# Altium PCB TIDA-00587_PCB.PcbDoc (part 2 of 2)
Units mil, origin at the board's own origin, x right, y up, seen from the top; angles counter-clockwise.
Board outline 4500 x 1700 mil, 4 copper layers (Top Layer, MidLayer1, MidLayer2, Bottom Layer), stack 61.6 mil thick; 120 components, 70 nets, 360 pads, 146 vias.
Unrouted connection lines stored in the file: 1.
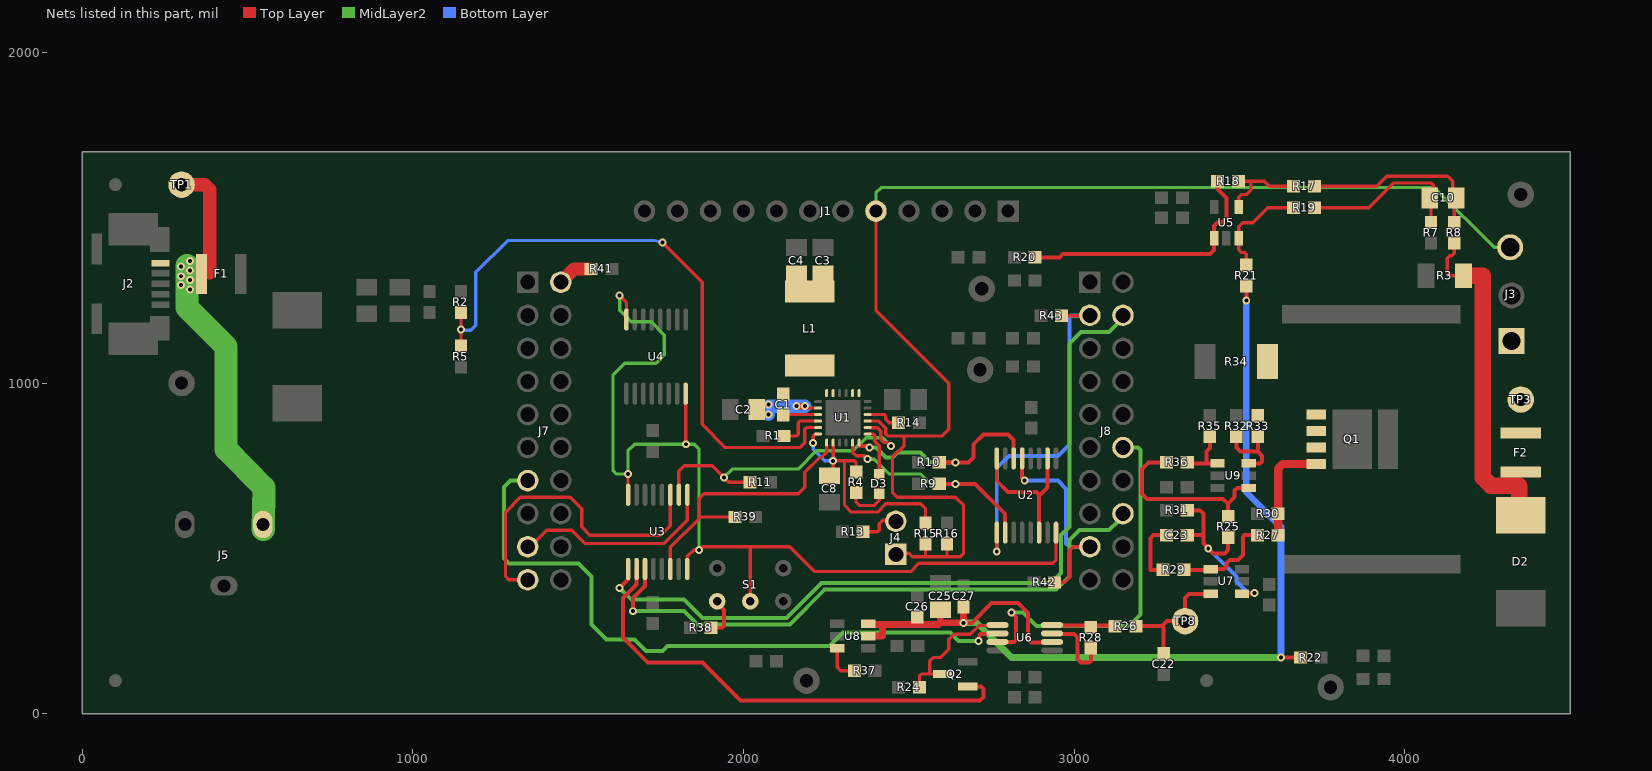
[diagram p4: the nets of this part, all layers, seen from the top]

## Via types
v1: diameter 24, hole 12, Top Layer to Bottom Layer, 141 vias
v2: diameter 50, hole 28, Top Layer to Bottom Layer, 4 vias
v3: diameter 50, hole 28, Top Layer to Bottom Layer, tented bottom, 1 vias

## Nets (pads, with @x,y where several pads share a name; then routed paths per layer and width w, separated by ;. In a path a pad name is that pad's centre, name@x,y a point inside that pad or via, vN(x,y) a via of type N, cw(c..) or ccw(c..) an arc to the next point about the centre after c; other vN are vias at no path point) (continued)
I2C_SCL_A: J8.17 R42.2 U2.13 | length 662.5
  Top Layer w10: R42.2@2940.5,397 2971,397 2985,411 2985,492.93 2997.07,505 J8.17@3050,505
  Top Layer w12: U2.13@2842.2,772.2 2842.2,712.8 v1(2850,705)
  Bottom Layer w12: v1(2850,705) 2950,705 2975,680 2975,515 2985,505 3025,505 J8.17@3050,480
I2C_SDA_A: J8.3 R43.2 U2.1 | length 1111.3
  Top Layer w10: R43.2@2961.5,1204 3049,1204 J8.3@3050,1205
  Top Layer w12: v1(2765.43,490.43) U2.1@2765.43,547.8
  Bottom Layer w12: v1(2765.43,490.43) 2765.43,743.24 2802.2,780 2950.82,780 2985,814.18 2985,1200 2990,1205 3025,1205 J8.3@3050,1180
INT_1: J7.19 U3.3 | length 982
  Top Layer w10: J7.19@1350,380 1325,405 1290,405 1280,415 1280,610 1325,655 1475,655 1510,620 1510,565 1535,540 1750,540 1778.39,568.39 U3.3@1778.39,662.2
INT_2: J7.17 U3.1 | length 644.9
  Top Layer w10: J7.17@1350,480 1350,500 1405,555 1480,555 1520,515 1759.13,515 1829.57,585.43 U3.1@1829.57,662.2
LDO: C8.2 R4.1 R15.2 U1.2 U1.24 | length 759.2
  Top Layer w10: v1@2210.49,820 2210,820.49 2210,840 2215.79,845.79 U1.24@2225.2,845.79 ; C8.2@2270.47,720.47 v1(2270.47,765) ; U1.2@2270.47,810 v1(2270.47,765) ; 2340,751.5 2340,759.98 2334.98,765 2305,765 ; R15.2@2550,566.5 R15.2@2550,576.5 2550,620 2535,635 2430,635 2405,610 2325,610 2305,630 2305,765 ; v1(2270.47,765) 2305,765
  Bottom Layer w10: v1(2210.25,818.55) 2210.25,799.75 2245,765 v1(2270.47,765)
NetC1_1: C1.1 L1.1 U1.17 U1.18
NetC1_2: C1.2 U1.21 | length 95
  Top Layer w10: C1.2@2120,905 U1.21@2215,905
NetC2_2: C2.2 U1.20 | length 202.3
  Top Layer w10: v1@2180,930 2185.47,924.53 U1.20@2215,924.53
  Top Layer w20: v1(2160,930) v1(2185,930)
  Bottom Layer w25: v1@2075,930 v1(2075,935)
  Bottom Layer w40: v1(2075,905) 2075,930 v1(2185,930)
NetC3_1: C3.1 C4.1 L1.2 U1.13 U1.14
NetC10_1: C10.1 R8.1 R17.2 | length 565.6
  Top Layer w10: R17.2@3726.5,1595 3915,1595 3945,1625 4130,1625 4144.53,1610.47 C10.1@4144.53,1560 ; C10.1@4148.23,1564.45 4148.7,1563.98 R8.1@4148.7,1485.94
NetC10_2: C10.2 R7.1 R19.2 | length 509.4
  Top Layer w10: R19.2@3726.5,1530 3890,1530 3965,1605 4080,1605 4085.47,1599.53 C10.2@4085.47,1560.75 ; R7.1@4078.7,1485.94 4078.7,1553.98 C10.2@4085.47,1560.75 ; C10.2@4085.47,1560 C10.2@4085.47,1560.75
NetC22_1: C22.1 R26.2 TP8.1 U7.3 | length 395.7
  Top Layer w12: R26.2@3186.5,265 3265,265 ; C22.1@3270,181.5 3270,260 3265,265 ; U7.3@3415,363 3414,362 3347,362 3335,350 TP8.1@3335,280 3280,280 3265,265
NetC23_1: C23.1 R29.1 | length 186.1
  Top Layer w12: R29.1@3268.5,435 3230,435 3230,530 3240,540 C23.1@3278.5,540
NetC23_2: C23.2 R25.2 R31.1 U7.4 | length 569.8
  Top Layer w12: C23.2@3341.5,540 3390,540 ; R31.1@3341.5,615 3380,615 3390,605 3390,540 ; R25.2@3465,533.5 3465,495 3455,485 3420,485 v1(3405,500) 3390,515 3390,540 ; U7.4@3502,363 3538,363 3540,365 v1(3545,365)
  Bottom Layer w12: v1(3405,500) 3490,415 3490,400 3525,365 v1(3545,365)
NetD2_1: D2.1 F2.1 R3.2 R8.2 | length 1023.6
  Top Layer w10: R8.2@4148.7,1422.95 4148.7,1392.13 4141.57,1385 4135,1385 4128,1378 4128,1336.13 4139.69,1324.45 R3.2@4177.09,1324.45
  Top Layer w50: R3.2@4177.09,1324.45 4235.55,1324.45 4235.55,714.07 4259.62,690 4346,690 4346,614.49 D2.1@4350,610.49
NetD3_1: D3.1 R4.2 | length 149.3
  Top Layer w10: R4.2@2340,673.5 R4.2@2340,668.5 2340,640 2350,630 2395,630 2410,645 D3.1@2410,665.47 D3.1@2410,680.47
NetD3_2: D3.2 U1.7 | length 131
  Top Layer w10: U1.7@2374.8,845.79 2392.21,845.79 2396,842 2396,824 2410,810 D3.2@2410,739.53
NetF1_1: F1.1 J2.1 J5.1 TP1.1 | length 1279.8
  Top Layer w12: F1.1@360.94,1330 F1.1@360.94,1374.06
  Top Layer w40: TP1.1@300,1600 370,1600 385,1585 385,1333
  MidLayer2 w70: 317,1355 317,1312 317,1228 435,1110 435,800 549,684 J5.1@547,558
  other v1: 325,1283 299,1297 325,1312 299,1323 325,1340 299,1352 325,1369
NetF2_2: F2.2 J3.1 TP3.1
NetJ1_5: J1.5 J3.3 J4.1 R15.1 R16.2 U1.9 | length 3947.3
  Top Layer w10: U1.9@2379.76,885.2 2385,885.2 2408.59,885.2 2430,863.79 2430,845 2435,840 2485,840 ; J1.5@2400,1520 2400,1220 2620,1000 2620,860 2600,840 2485,840 ; J4.1@2460,485 2500,485 2510,475 2550,475 ; R15.1@2550,503.5 2550,475 ; R16.2@2615,503.5 2615,475 ; 2485,840 2485,810 2450,775 2450,670 2465,655 2640,655 2665,630 2665,485 2655,475 2615,475 ; 2550,475 2615,475
  MidLayer2 w10: J1.5@2400,1520 2400,1575 2416.3,1591.3 4088.7,1591.3 4269.41,1410.59 J3.3@4350,1410.59
NetJ4_2: J4.2 R13.2 | length 124.7
  Top Layer w10: R13.2@2361.5,550 2405,550 2410,555 2410,575 2420,585 J4.2@2460,585
NetJ7_2: J7.2 R41.2 | length 108.1
  Top Layer w40: J7.2@1447,1305 1487,1345 R41.2@1538.5,1345
NetQ1_1: Q1.1 Q1.2 Q1.3 R33.2 R34.2
NetQ1_4: Q1.4 R27.2 R30.2 | length 321.9
  Top Layer w25: R27.2@3616.5,540 R30.2@3616.5,605 3616.5,741.5 3630,755 Q1.4@3731.34,755
NetQ2_3: Q2.3 R24.2 U6.5 | length 420.4
  Top Layer w10: R24.2@2531.5,80 2531.5,113.76 2537.74,120 2563.23,120 ; Q2.3@2602.6,120 2563.23,120 ; U6.5@2774.4,266.8 2711.8,266.8 2685,240 2635,240 2620,225 2620,195 2595,170 2573.23,170 2563.23,160 2563.23,120
NetR1_2: R1.2 U1.22 | length 137.7
  Top Layer w10: R1.2@2121.5,840 2160,840 2165,845 2165,880 2170,885 U1.22@2220.04,885
NetR2_1: R2.1 R5.2 U1.23 | length 1937.8
  Top Layer w10: R5.2@1145,1110 R5.2@1145,1111.5 v1(1145,1162.5) R2.1@1145,1213.5 ; v1(1755,1425) 1875,1305 1875,875 1945,805 2170,805 2185,820 2185,860 2190.5,865.5 U1.23@2215,865.5
  Bottom Layer w10: v1(1145,1162.5) 1147.5,1160 1175,1160 1190,1175 1190,1335 1286,1431 1662.61,1431 1670.43,1431 ; 1671.04,1431 1731,1431 v1(1755,1425)
NetR14_2: R14.2 U1.10 | length 105.1
  Top Layer w10: U1.10@2379.65,905 2425,905 2430,900 2430,890.02 2440.02,880 R14.2@2468.5,880
NetR17_1: R17.1 R18.1 U5.4 | length 279.6
  Top Layer w10: R18.1@3491.5,1610 R18.1@3496.5,1610 3533.25,1610 ; U5.4@3497.4,1532.24 3497.4,1562.4 3505,1570 3520,1570 3533.25,1583.25 3533.25,1610 ; R17.1@3663.5,1595 3590,1595 3575,1610 3533.25,1610
NetR18_2: R18.2 R20.2 U5.1 | length 791.7
  Top Layer w12: R20.2@2881.5,1380 2955,1380 2965,1390 3410,1390 3422.6,1402.6 U5.1@3422.6,1437.76 3422.6,1475.16 3432.44,1485 3445,1485 3460,1500 3460,1560 3433.5,1586.5 R18.2@3433.5,1610
NetR19_1: R19.1 R21.1 U5.3 | length 321.2
  Top Layer w10: R21.1@3520,1356.5 3520,1390 3515,1395 3505,1395 3497.4,1402.6 U5.3@3497.4,1437.76 3497.4,1472.56 3509.84,1485 3540,1485 3585,1530 R19.1@3663.5,1530
NetR25_1: R25.1 R36.1 U9.1 | length 559.3
  Top Layer w12: R36.1@3278.5,760 3225,760 3205,740 3205,665 3220,650 3450,650 3465,635 ; R25.1@3465,596.5 3465,635 ; U9.1@3525,683 3493,683 3485,675 3485,655 3465,635
NetR26_1: R26.1 R28.2 U6.4 | length 181.5
  Top Layer w12: U6.4@2940.2,266.8 R26.1@3121.7,266.8
NetR27_1: R27.1 R29.2 U7.1 | length 303.6
  Top Layer w12: R29.2@3331.5,435 3413,435 3415,437 3452,437 3460,445 3460,455 3470,465 3495,465 3510,480 3510,535 3515,540 R27.1@3553.5,540
NetR28_1: R28.1 U6.3 | length 224.2
  Top Layer w12: U6.3@2940.2,241.2 2998.8,241.2 3010,230 3010,165 3020,155 3045,155 3050,160 R28.1@3050,198.5
NetR32_1: R32.1 R33.1 U9.3 | length 229.8
  Top Layer w12: R32.1@3490,838.5 3490,805 3502,793 3555,793 ; U9.3@3525,757 3562,757 3568,763 3568,780 3555,793 ; R33.1@3555,838.5 3555,793
NetR35_1: R35.1 R36.2 U9.4 | length 183.4
  Top Layer w12: R36.2@3341.5,760 3344.5,757 3400,757 ; R35.1@3410,838.5 3410,803 3400,793 3400,757 ; U9.4@3438,757 3400,757
NetR37_1: R37.1 U8.3 | length 90.7
  Top Layer w10: U8.3@2282.76,197.6 2282.76,140.24 2293,130 2311.82,130
NetR38_1: R38.1 S1.4 | length 123.9
  Top Layer w12: R38.1@1901.5,260 1935,260 1940,265 1940,313.41 1920,333.41 S1.4@1920,340
NetR39_2: R39.2 U1.1 U3.14 | length 836.5
  Top Layer w10: U3.14@1778.39,437.8 1778.39,503.39 1865,590 ; 1865,595 1865,650 1880,665 2165,665 2185,685 2185,730 2229.9,774.9 2234.9,774.9 2251.3,791.3 U1.1@2251.3,810 ; 1870,595 R39.2@1973.5,595
NetS1_5: S1.5 U2.8 U3.8 U3.16 U4.8 U4.16 | length 3150.1
  Top Layer w10: v1(1625,1265) 1645.43,1244.57 U4.8@1645.43,1192.2 ; U3.8@1650.43,662.2 v1@1650.43,724.57 ; U4.16@1824.57,967.8 1824.57,815.43 v1(1825,815) ; U3.16@1829.57,437.8 1829.57,476.14 1848.43,495 v1(1865,495) 1875,505 2020,505 ; S1.5@2020,340 2020,505 ; U2.8@2944.57,547.8 2944.57,464.57 2935,455 2530,455 2505,430 2215,430 2140,505 2020,505
  MidLayer2 w10: v1(1625,1265) 1625,1220 1660,1185 1720,1185 1760,1145 1760,1085 1735,1060 1640,1060 1605,1025 1605,735 1615,725 v1(1650,725) 1650,795 1670,815 v1(1825,815) 1850,815 1865,800 v1(1865,495)
NetU2_6: U2.6 U2.10 U2.16 | length 450.3
  Top Layer w12: U2.16@2765.43,772.2 2765.43,704.57 2800,670 2885,670 2893.39,661.61 ; U2.6@2893.39,547.8 2893.39,661.61 ; U2.10@2918.98,772.2 2918.98,683.98 2896.61,661.61 2893.39,661.61
SCL: R10.1 R11.1 U1.6 U1.8 U2.14 U3.2 | length 1651
  Top Layer w10: U3.2@1803.98,662.2 1803.98,733.98 1820,750 1905,750 v1(1940,715) 1955,700 R11.1@2018.5,700 ; U1.8@2380.28,865 2405,865 2415,855 2415,830 2425,820 2435,820 v1(2445,810)
  Top Layer w12: U1.6@2349.8,810 2375,810 v1(2380,805) ; R10.1@2591.5,760 v1(2640,760) 2680,760 2695,775 2695,815 2725,845 2800,845 2816.61,828.39 U2.14@2816.61,772.2
  MidLayer2 w10: v1(1940,715) 1965,740 2165,740 2220,795 2330.1,795 2370.1,835 2420,835 v1(2445,810)
  MidLayer2 w12: v1(2380,805) 2400,805 2430,775 2450,775 2465,790 2535,790 2565,760 v1(2640,760)
SCLK: J7.13 U6.6 | length 2058.3
  Top Layer w12: v1@2713,220 2713,237.8 2716.4,241.2 U6.6@2774.4,241.2
  MidLayer2 w12: J7.13@1350,680 1325,705 1295,705 1275,685 1275,470 1290,455 1500,455 1540,415 1540,270 1585,225 1670,225 1705,190 1755,190 1770,205 2260,205 2300,245 2625,245 2650,220 v1(2710,220)
SDA: R9.1 U1.5 U2.2 | length 662.7
  Top Layer w10: U1.5@2330.1,810 2330.1,789.9 2340,780 2365,780 v1(2375,770)
  Top Layer w12: R9.1@2591.5,695 v1(2640,695) 2700,695 2791.02,603.98 U2.2@2791.02,547.8
  MidLayer2 w10: v1(2375,770) 2395,770 2440,725 2535,725 2565,695 v1(2640,695)
SIMO: J8.12 U6.7 | length 1141
  Top Layer w12: U6.7@2756.6,216.6 2817.6,216.6 2824,223 2824,292 v1(2810,306)
  MidLayer2 w12: v1(2810,306) 2844,306 2885,265 3165,265 3200,300 3200,797 3192,805 3175,805 J8.12@3150,780
SYNC: Q2.1 U3.10 | length 1473.4
  Top Layer w12: U3.10@1676.02,437.8 1676.02,391.02 1635,350 1635,230 1710,155 1875,155 1990,40 2715,40 2725,50 2725,75 2717.4,82.6 Q2.1@2677.4,82.6
SYNC_1: J8.16 U3.11 | length 1837.4
  Top Layer w12: v1(1665,310) 1665,350 1701.61,386.61 U3.11@1701.61,437.8
  MidLayer2 w12: v1(1665,310) 1820,310 1860,270 2140,270 2245,375 2945,375 2985,415 2985,525 3015,555 3105,555 3130,580 J8.16@3150,580
SYNC_2: J8.4 U3.9 | length 2391.7
  Top Layer w12: v1(1625,380) 1650.43,405.43 U3.9@1650.43,437.8
  MidLayer2 w12: v1(1625,380) 1660,345 1820,345 1875,290 2130,290 2235,395 2930,395 2960,425 2960,540 2985,565 2985,1120 3020,1155 3105,1155 3130,1180 J8.4@3150,1180
VREF: C25.2 C26.1 C27.1 R21.2 R22.2 U6.2 U8.5 U8.6 | length 3086.5
  Top Layer w12: v1(2665,275) 2690,275 2750,335 2830,335 2860,305 2860,225 2869.4,215.6 U6.2@2940.2,215.6 ; v1(3520,1250) R21.2@3520,1293.5 ; v1(3625,170) R22.2@3683.5,170
  Top Layer w20: U8.6@2382,270 2420,270 ; U8.5@2387,235 2420,235 2420,270 ; C26.1@2525,275 C26.1@2525,289.08 ; C25.2@2595,325.47 C25.2@2595,315 2595,275 ; v1@2660,275 2595,275 ; v1(2665,275) C27.1@2665,323.5 ; 2420,270 2590,270 2595,275
  MidLayer2 w20: v1(2665,275) 2705,275 2810,170 v1(3625,170)
  Bottom Layer w20: v1(3520,1250) 3520,670 3625,565 v1(3625,170)
pads on no net: FID1.1 FID2.1 FID3.1 J1.6 J1.7 J1.8 J2.2 J2.3 J2.4 J7.3 J7.5 J7.7 J7.11 J8.1 J8.5 J8.6 J8.7 J8.8 J8.9 J8.10 J8.11 J8.13 J8.14 J8.15 J8.19 LBL1.0 S1.1 S1.3 U2.3 U2.7 U2.9 U2.15 U4.9 U4.10 U4.11

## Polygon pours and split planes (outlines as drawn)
GND on Top Layer "Top Layer-No Net" (solid, pour order 8): 1078.54,1230 828.5,1230 828.5,1048.5 800,1020 410,1020 300,1130 290,1140 290,1240 190,1240 190,1190 110,1190 110,910 150,870 170,850 480,850 530,800 540,810 890,810 1080,1000 1080,1230
GND on Top Layer "Top Layer-No Net 1" (solid, remove dead copper, pour order 7): 21.18,1689 4466.18,1689 4466.18,20 21.18,20
GND on MidLayer1 "MidLayer1-No Net" (solid, pour order 6): 25,1683 4470,1683 4470,30 25,30
GND on MidLayer2 "MidLayer2-No Net" (solid, remove dead copper, pour order 9): 25,1672 4470,1672 4470,25 25,25
GND on Bottom Layer "Bottom Layer-No Net" (solid, remove dead copper, pour order 10): 25,1680 4470,1680 4470,25 25,25

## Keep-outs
Keep-Out Layer:
  lines w10: -20,1715 -15,-15 4515,-15 4515,1715 -20,1715
  text ".Layer_Name" at 577,-858.49 h60

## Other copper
Top Layer:
  rectangle net GND: 2285,935 2315,982
  rectangle net GND: 2285,808 2315,850
  rectangle net GND: 1905,890 1985,950
  rectangle net NetC1_1: 2100,950 2165,1085
  rectangle net NetC2_2: 2010,890 2090,950
  rectangle net NetC1_1: 2245,965 2277,1040
  rectangle net NetC3_1: 2120,1230 2360,1360
  rectangle net 5VDC: 455,1165 779.92,1405
  rectangle net 5VDC: 645,1260 1165,1405
  rectangle net 5VDC: 2175,949.21 2230,1010
  rectangle net NetC3_1: 2324,965 2360,1355
  rectangle net CHG/LOAD: 2370,918 2470,950
  rectangle net NetQ1_1: 3539.21,880 3765,1135.87
  rectangle net NetQ1_1: 3645,785 3765,915
  rectangle net CHG/LOAD: 3780,210 4040,1447.52
  rectangle net CHG/LOAD: 4027.48,1185 4090,1370.71
  rectangle net CHG/LOAD: 4020,210 4170,1260
  rectangle net CHG/LOAD: 3625,1155 3805,1450
  rectangle net CHG/LOAD: 3665,440 3820,723.7
  rectangle net CHG/LOAD: 3630,211.89 3800,475
  rectangle net NetF2_2: 4280.98,834 4415,1185
  rectangle net NetD2_1: 4285,620 4415,750
  rectangle net CHG/LOAD: 2400,918 2482,1105
  rectangle net ADC_CH_VDC: 2690,1030 2835,1153.7
  rectangle net ADC_CH_IDC: 2695,1281.46 2840,1400
  rectangle net GND: 2125,1380 2280,1465
  rectangle net 5VDC: 460,1375 1686.11,1442
  rectangle net GND: 4275,215 4425,385
  rectangle net GND: 3270,975 3465,1220
  rectangle net NetQ1_1: 3510,994.13 3610,1220
  rectangle net GND: 2465,1485 2835,1555
  rectangle net GND: 78.98,1416.14 350,1530
  rectangle net NetF1_1: 284.02,1264.07 405,1391.02
  rectangle net NetF1_1: 209,1352 299,1383
  text ".CopyrightYear" at 1268,1560 h60
  text "TI" at 1544,1560 h60
  text "©" at 1175,1557 h105
  text ".Layer_Name" at 577,-858.49 h60
Bottom Layer:
  text "UL94V-0" at 1575,1545 h60
  text "MADE IN U.S." at 1585,1450 h60
  text ".Layer_Name" at 577,-858.49 h60

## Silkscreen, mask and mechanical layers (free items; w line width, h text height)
Top Overlay:
  text "+" at 194,1575 h40
  text "-" at 4425,1570 h40
  text "-" at 4198,1229 h40
  text "+" at 4199,1108 h40
  text "-" at 194,976 h40
  text "+" at 4375,860 h40
  text "4.5Vdc-6Vdc" at 39,812 h40
  text "Load/Batt" at 4485,690 h40 r90
  text "UNIT 1" at 1880,490 h40
  text "-TS" at 2315,405 h40
  text "UNIT 2" at 1985,250 h40
  text "bq24250RGE" at 668,173 h90
  text "Booster Pack Charger" at 168,56 h90
  text ".Layer_Name" at 577,-858.49 h60
Bottom Overlay:
  rectangle: 219,50 519,150
  text ".PCB_Rev" at 195,70 h60
  text ".PRJ_Number" at 1185,60 h60
  text "-" at 584,49.5 h60
  text ".Layer_Name" at 577,-858.49 h60
Top Paste:
  text ".Layer_Name" at 577,-858.49 h60
Bottom Paste:
  text ".Layer_Name" at 577,-858.49 h60
Top Solder:
  rectangle: 3840,210 3970,255
  text ".Layer_Name" at 577,-858.49 h60
  text ".Layer_Name" at 577,-858.49 h60
Bottom Solder:
  text ".Layer_Name" at 577,-858.49 h60
Drill Guide:
  text ".Layer_Name" at 577,-858.49 h60
M1 Board Outline:
  the board outline again, w10
  text ".Layer_Name" at 577,-858.49 h60
M2 Board Dimensions:
  rectangle: -0.5,-285.5 124.5,-160.5
  rectangle: 124.5,-410.5 499.5,-285.5
  lines w7: -0.5,-285.5 999.5,-285.5 ; 124.5,-410.5 124.5,-160.5 ; 249.5,-410.5 249.5,-160.5 ; 499.5,-410.5 499.5,-160.5 ; 749.5,-410.5 749.5,-160.5 ; -0.5,-410.5 999.5,-410.5 999.5,-160.5 -0.5,-160.5 -0.5,-410.5
  lines w10: -0.5,-475.5 -0.5,-455.5 ; 59.5,-485.5 -0.5,-465.5 ; 59.5,-445.5 -0.5,-465.5 ; 223.58,-465.5 -0.5,-465.5 ; 775.42,-465.5 999.5,-465.5 ; 939.5,-485.5 999.5,-465.5 ; 939.5,-445.5 999.5,-465.5 ; 999.5,-475.5 999.5,-455.5
  text "1000 (mil)" at 233.58,-501.49 h60
  text ".Layer_Name" at 577,-858.49 h60
M3 3D STEP Top:
  text ".Layer_Name" at 577,-858.49 h60
M4 3D STEP Bottom:
  text ".Layer_Name" at 577,-858.49 h60
M5 Assembly Top:
  lines w10: -292,-930.17 6308,-930.17 ; -292,-726.83 6310,-726.83 ; -292,-523.5 -292,-1133.5 3713,-1133.5 6310,-1133.5 6310,-523.5 -291.5,-523.5 -291.5,-1133.5 1284,-1133.5 ; 2173,-1133.5 2173,-523.5 ; 3440,-726.83 3440,-523.5 ; 4280,-726.83 4280,-523.5 ; 4902,-1140 4902,-937.17
  text "COMPONENTS MARKED 'DNP' SHOULD NOT BE POPULATED." at 1153.5,-318.5 h60
  text "ASSEMBLY VARIANT:" at 1153,-434 h60
  text ".VariantName" at 2189,-434 h60
  text "PCB VIEWED FROM TOP SIDE" at -228.5,-655.67 h60
  text "BOARD #:" at 2248,-655.67 h60
  text ".PRJ_Number" at 2793.5,-655.67 h60
  text "REV:" at 3638,-655.67 h60
  text ".PCB_Rev" at 3929.5,-655.67 h60
  text "SVN REV:" at 4476,-655.67 h60
  text ".VersionControl_RevNumber" at 4982,-655.67 h60
  text "IGNORE ->" at -228.5,-858.49 h60
  text "PLOT NAME =" at -228.5,-1064.34 h60
  text ".plot_File_Name" at 577,-1064.34 h60
  text "GENERATED    :" at 2250,-1064.34 h60
  text ".Print_Date" at 3119.5,-1064.34 h60
  text ".Print_Time" at 3848.5,-1064.34 h60
  text "TEXAS INSTRUMENTS" at 5113,-1064.34 h60
M6 Assembly Bottom:
  lines w10: -292.5,-727.33 6309.5,-727.33 ; -290.5,-930.67 6309.5,-930.67 ; 1115.5,-1140.5 1115.5,-937.67 ; 1737.5,-727.33 1737.5,-524 ; 2577.5,-727.33 2577.5,-524 ; 3844.5,-1134 3844.5,-524 ; 4733.5,-1134 6309,-1134 6309,-524 -292.5,-524 -292.5,-1134 2304.5,-1134 6309.5,-1134 6309.5,-524
  text "COMPONENTS MARKED 'DNP' SHOULD NOT BE POPULATED." at 6102,-318 h60
  text ".VariantName" at 5058,-434 h60
  text "ASSEMBLY VARIANT:" at 6097,-434 h60
  text ".VersionControl_RevNumber" at 1035.5,-656.17 h60
  text "SVN REV:" at 1541.5,-656.17 h60
  text ".PCB_Rev" at 2088,-656.17 h60
  text "REV:" at 2379.5,-656.17 h60
  text ".PRJ_Number" at 3224,-656.17 h60
  text "BOARD #:" at 3769.5,-656.17 h60
  text "PCB VIEWED FROM BOTTOM SIDE" at 6246,-656.17 h60
  text "IGNORE ->" at 2547.85,-858.49 h60
  text "TEXAS INSTRUMENTS" at 904.5,-1064.84 h60
  text ".Print_Time" at 2169,-1064.84 h60
  text ".Print_Date" at 2898,-1064.84 h60
  text "GENERATED    :" at 3767.5,-1064.84 h60
  text ".plot_File_Name" at 5440.5,-1064.84 h60
  text "PLOT NAME =" at 6246,-1064.84 h60
M9 Title Sheet:
  drawing of 57 lines, arcs and shapes, not listed
  text "1" at 739.84,8036.5 h70
  text "2" at 3235.5,8036.5 h70
  text "3" at 5724.84,8036.5 h70
  text "4" at 8231.51,8036.5 h70
  text "5" at 10730.5,8036.5 h70
  text "6" at 13235.5,8036.5 h70
  text "A" at -416.5,6893.5 h70
  text "A" at 14383.5,6893.5 h70
  text "B" at -416.5,4513.5 h70
  text "B" at 14383.5,4513.5 h70
  text "C" at -416.5,2138.5 h70
  text "C" at 14383.5,2138.5 h70
  text "PROJECT TITLE:" at 11343.5,277.5 h45
  text ".PRJ_Title" at 11393.5,144.17 h70
  text "DESIGNED FOR:" at 11343.5,-23.5 h45
  text ".PRJ_Customer" at 11393.5,-163.5 h70
  text "D" at -416.5,-231.5 h70
  text "D" at 14383.5,-231.5 h70
  text "FILE NAME:" at 11343.5,-323.5 h45
  text ".PCB_File_Name_No_Path" at 11393.5,-443.5 h70
  text "Texas Instruments (TI) and/or its licensors do not warrant the accuracy or completeness of this specification" at 6374,-605.34 h45
  text "ENGINEER:" at 11343.5,-613.5 h45
  text "LAYOUT BY:" at 12848.5,-613.5 h45
  text "or any information contained therein. TI and/or its licensors do not warrant that this design will meet" at 6329.01,-718 h45
  text ".PRJ_Engineer" at 11393.5,-768.49 h70
  text ".PCB_Layout" at 12899,-768.49 h70
  text "the specifications, will be suitable for your application or fit for any particular purpose, or will operate in" at 6329.01,-830.67 h45
  text ".Layer_Name" at 577,-858.49 h60
  text "ALTIUM DESIGNER VERSION:" at 12848.5,-923.5 h45
  text "an implementation. TI and/or its licensors do not warrant that the design is production worthy. You should" at 6329.01,-943.33 h45
  text "completely validate and test your design implementation to confirm the system functionality for your application." at 6374,-1056 h45
  text ".print_Scale" at 11393.5,-1056.83 h70
  text ".Application_BuildNumber" at 12899,-1056.83 h70
  text "1" at 739.84,-1263.5 h70
  text "2" at 3235.5,-1263.5 h70
  text "3" at 5724.84,-1263.5 h70
  text "4" at 8231.51,-1263.5 h70
  text "5" at 10730.5,-1263.5 h70
  text "6" at 13235.5,-1263.5 h70
M10 Fab Notes:
  drawing of 222 lines, arcs and shapes, not listed
  text "Layer Stack Up Detail for: PR2182E1_PCB.PcbDoc" at 11369,7671.25 h42
  text "Layer" at 11369,7612.2 h22
  text "Gerber" at 12362.5,7612.2 h22
  text "Copper" at 13056.16,7612.2 h22
  text "Dielectric" at 13785.74,7612.2 h22
  text "Name" at 11369,7568.2 h22
  text "Document" at 12362.5,7568.2 h22
  text "Thickness" at 13056.16,7568.2 h22
  text "Material" at 13785.74,7568.2 h22
  text "Top Solder Mask" at 11369,7506.88 h31
  text "(.GTS)" at 12362.5,7506.88 h31
  text "Solder Resist" at 13785.74,7506.88 h31
  text "Top Layer" at 11369,7420.62 h31
  text "(.GTL)" at 12362.5,7420.62 h31
  text "1.4mil" at 13056.16,7420.62 h31
  text "FR-4" at 13785.74,7377.5 h31
  text "MidLayer1" at 11369,7334.38 h31
  text "(.G1)" at 12362.5,7334.38 h31
  text "1.4mil" at 13056.16,7334.38 h31
  text "FR-4" at 13785.74,7291.25 h31
  text "MidLayer2" at 11369,7248.12 h31
  text "(.G2)" at 12362.5,7248.12 h31
  text "1.4mil" at 13056.16,7248.12 h31
  text "FR-4" at 13785.74,7205 h31
  text "Bottom Layer" at 11369,7161.88 h31
  text "(.GBL)" at 12362.5,7161.88 h31
  text "1.4mil" at 13056.16,7161.88 h31
  text "Bottom Solder Mask" at 11369,7075.62 h31
  text "(.GBS)" at 12362.5,7075.62 h31
  text "Solder Resist" at 13785.74,7075.62 h31
  text "DESIGN INFORMATION" at 12381.02,6810 h60
  text "(REFER ALSO ARRAY/PANEL PROFILING INFORMATION)" at 12019.46,6648.29 h60
  text "BOARD SIZE" at 11333.46,6644 h60
  text "1690MIL" at 11795.78,6516.18 h60
  text "X" at 12301.46,6516.18 h60
  text "4500MIL" at 12532.78,6516.18 h60
  text "Number of Layers :" at 11736.46,6319 h60
  text "4" at 12831.27,6309 h60
  text "MIN. TRACK WIDTH:" at 11736.46,6180 h60
  text "6" at 12832.7,6180 h60
  text "MIL" at 12987.46,6180 h60
  text "MIN. CLEARANCE:" at 11736.46,6048 h60
  text "5" at 12832.7,6048 h60
  text "MIL" at 12987.46,6048 h60
  text "MIN. VIA PAD SIZE:" at 11736.46,5916 h60
  text "18" at 12802.71,5916 h60
  text "MIL" at 12987.46,5916 h60
  text "0.05mm (2MIL)" at 12431.46,5774.29 h60
  text "MINIMUM ANNULAR RING" at 11407.23,5770 h60
  text "EXTERNAL" at 13139.46,5770 h60
  text "PER" at 11607.23,5652 h60
  text "IPC-D-275 CLASS 2 LEVEL C" at 11827.23,5652 h60
  text "MIL, HOLES" at 13315.46,5539.71 h60
  text "+/-" at 12923,5539 h60
  text "+/-" at 13777,5539 h60
  text "REGISTRATION TOLERANCES:" at 11407.23,5534 h60
  text "METAL" at 12607,5534 h60
  text "5" at 13183.2,5534 h60
  text "3" at 14016.2,5534 h60
  text "MIL" at 14132.46,5534 h60
  text "MATERIAL:" at 11332.46,5324.54 h60
  text "FR-4 High Tg" at 12318.9,5184.21 h60
  text "FR-408" at 11753.46,5175.64 h60
  text "X" at 12165.46,5175.64 h60
  text "OTHER" at 13241.46,5175.64 h60
  text "62 MIL (1.6mm) +/-10%" at 12073.56,5012.92 h60
  text "THICKNESS:" at 11407.23,5008.64 h60
  text "X" at 11945.4,5008.64 h60
  text "OTHER" at 13358.46,5008.64 h60
  text "TOLERANCE:" at 11407.23,4850.64 h60
  text "X" at 12246.53,4850.64 h60
  text "ANSI IPC-6012 TYPE 3 CLASS 2" at 12433.48,4850.64 h60
  text "OTHER +/-" at 12433.46,4694.64 h60
  text "BOW & TWIST:" at 11407.23,4537.64 h60
  text "X" at 12246.53,4537.64 h60
  text "ANSI IPC-6012 TYPE 3 CLASS 2" at 12433.48,4537.64 h60
  text "OTHER +/-" at 12433.46,4379.13 h60
  text "COPPER THICKNESS (FINISHED):" at 11332.46,4243.64 h60
  text "1.4MIL (1oz)" at 12212.46,4090.92 h60
  text "2MIL (1.4oz)" at 12979.46,4090.92 h60
  text "2.8MIL (2oz)" at 13706.46,4090.92 h60
  text "OUTER:" at 11689.46,4086.64 h60
  text "X" at 13575,4080 h60
  text "1.4MIL (1oz)" at 12212.46,3933.92 h60
  text "2.8MIL (2oz)" at 12979.46,3933.92 h60
  text "N/A" at 13706,3934.29 h60
  text "INNER SIGNAL:" at 11400.38,3929.64 h60
  text "X" at 12860,3925 h60
  text "DRILLING:" at 11332.46,3790.64 h60
  text "REFERENCE:" at 11407.23,3673.64 h60
  text "X" at 12055.46,3673.64 h60
  text "AS SHOWN" at 12242.46,3673.64 h60
  text "X" at 12956.46,3673.64 h60
  text "NC_DRILL FILES" at 13093.46,3673.64 h60
  text "PTH MIN COPPER THICKNESS:" at 11407.23,3515.64 h60
  text "X" at 12757.46,3515.64 h60
  text "1MIL" at 12894.46,3515.64 h60
  text "OTHER" at 13391.46,3515.64 h60
  text "BOARD FINISH:" at 11332.46,3356.64 h60
  text "SILKSCREEN:" at 11487.68,3238.64 h60
  text "X" at 12436.46,3238.64 h60
  text "TOP" at 12562.46,3238.64 h60
  text "X" at 12946.46,3238.64 h60
  text "BOTTOM" at 13073.46,3238.64 h60
  text "SILKSCREEN COLOR:" at 11487.68,3071.64 h60
  text "X" at 12435.42,3071.64 h60
  text "WHITE" at 12562.46,3071.64 h60
  text "OTHER" at 13073.46,3071.64 h60
  text "SOLDER RESIST COLOR:" at 11487.68,2901.64 h60
  text "RED" at 13661.46,2752.44 h60
  text "GREEN" at 12182.46,2742.44 h60
  text "BLUE" at 12773.46,2742.44 h60
  text "OTHER" at 13311.46,2742.44 h60
  text "X" at 13160,2740 h60
  text "IMMERSION GOLD (ENIG)" at 12393.46,2553.92 h60
  text "ENEPIG" at 13731,2550.64 h60
  text "SURFACE FINISH:" at 11332.46,2549.64 h60
  text "X" at 12206.51,2549.64 h60
  text "IMM. TIN/SILVER OR EQUIV" at 11662,2392.64 h60
  text "OTHER" at 13093.46,2392.64 h60
  text "ARRAY/PANEL:" at 11332.46,2213.64 h60
  text "CUT AND TRIM PER MECH LAYER 1" at 12393.46,2209.35 h60
  text "N.C. ROUTE" at 12393.46,2057.64 h60
  text "X" at 13072.46,2057.64 h60
  text "V. SCORE" at 13259.46,2057.64 h60
  text "CERTIFICATION:" at 11332.46,1920.64 h60
  text "MATERIALS AND WORKMANSHIP FOR ALL PCBS" at 12057.46,1920.64 h60
  text "TO MEET OR EXCEED THE REQUIREMENTS OF:" at 12057.46,1822.64 h60
  text "X" at 11683.96,1686.13 h60
  text "ANSI IPC-A-600F CLASS ->" at 11822.96,1686.13 h60
  text "X" at 13462.02,1686.13 h60
  text "2" at 13580.96,1686.14 h60
  text "1" at 13265.96,1684.64 h60
  text "3" at 13934.96,1684.64 h60
  text "X" at 11686.02,1526.64 h60
  text "UL 94V-0" at 11822.96,1526.64 h60
  text "X" at 12498.02,1526.64 h60
  text "RoHS" at 12634.96,1526.64 h60
  text "OTHER" at 13279.36,1526.64 h60
  text "PER ORDER" at 13676.42,1526.64 h60
  text "ADDITIONAL REQUIREMENTS:" at 11332.46,1385.64 h60
  text "MICROSECTION:" at 11407.23,1270.64 h60
  text "YES" at 12312.96,1270.64 h60
  text "REQUIRED" at 13174.46,1114.49 h60
  text "BARE BOARD ELEC. TEST:" at 11407.23,1111.64 h60
  text "NONE" at 12712.96,1111.64 h60
  text "X" at 13047.46,1111.64 h60
  text "PER ORDER" at 13766.46,1111.64 h60
  text "MANUFACTURER'S UL:" at 11407.23,954.64 h60
  text "RAIL" at 12572.96,950.35 h60
  text "METAL" at 13064.77,950.35 h60
  text "X" at 13440,950 h60
  text "SILK" at 13576.46,950.35 h60
  text ".Layer_Name" at 577,-858.49 h60
M11 Gerber Information:
  lines w10: -292,-930.17 6308,-930.17 ; -292,-726.83 6310,-726.83 ; -292,-523.5 -292,-1133.5 3713,-1133.5 6310,-1133.5 6310,-523.5 -291.5,-523.5 -291.5,-1133.5 1284,-1133.5 ; 2173,-1133.5 2173,-523.5 ; 3440,-726.83 3440,-523.5 ; 4280,-726.83 4280,-523.5 ; 4902,-1140 4902,-937.17
  text "ALL ARTWORK VIEWED FROM TOP SIDE" at -228.5,-655.67 h60
  text "BOARD #:" at 2248,-655.67 h60
  text ".PRJ_Number" at 2793.5,-655.67 h60
  text "REV:" at 3638,-655.67 h60
  text ".PCB_Rev" at 3929.5,-655.67 h60
  text "SVN REV:" at 4476,-655.67 h60
  text ".VersionControl_RevNumber" at 4982,-655.67 h60
  text "LAYER NAME =" at -228.5,-858.49 h60
  text "PLOT NAME =" at -228.5,-1064.34 h60
  text ".plot_File_Name" at 577,-1064.34 h60
  text "GENERATED    :" at 2250,-1064.34 h60
  text ".Print_Date" at 3119.5,-1064.34 h60
  text ".Print_Time" at 3848.5,-1064.34 h60
  text "TEXAS INSTRUMENTS" at 5113,-1064.34 h60
M12 Stackup:
  text "The Stackup Legend below this is static." at 11605.5,7874.5 h60
  text "If you change the stackup, update the Legend." at 11615.5,7784.5 h60
  text ".Layer_Name" at 577,-858.49 h60
M13 Component Bodies Top:
  text ".Layer_Name" at 577,-858.49 h60
M14 Component Bodies Bottom:
  text ".Layer_Name" at 577,-858.49 h60
M15 Courtyards Top:
  text ".Layer_Name" at 577,-858.49 h60
M16 Courtyards Bottom:
  text ".Layer_Name" at 577,-858.49 h60
Drill Drawing:
  circle w3.33: c5197.72,2076.72 r24.89
  lines w3.33: 5172.83,1155.92 5222.6,1155.92 5222.6,1205.69 5172.83,1205.69 5172.83,1155.92 ; 5172.83,1330.12 5197.72,1305.24 5222.6,1330.12 5197.72,1355.01 5172.83,1330.12 ; 5172.83,1454.56 5172.83,1467 5185.27,1479.44 5172.83,1491.89 5172.83,1504.33 5185.27,1504.33 5197.72,1491.89 5210.16,1504.33 5222.6,1504.33 5222.6,1491.89 5210.16,1479.44 5222.6,1467 5222.6,1454.56 5210.16,1454.56 5197.72,1467 5185.27,1454.56 5172.83,1454.56 ; 5172.83,1616.32 5185.27,1616.32 5185.27,1603.88 5210.16,1603.88 5210.16,1616.32 5222.6,1616.32 5222.6,1641.21 5210.16,1641.21 5210.16,1653.65 5185.27,1653.65 5185.27,1641.21 5172.83,1641.21 5172.83,1616.32 ; 5172.83,1753.2 5197.72,1765.64 5222.6,1753.2 5210.16,1778.08 5222.6,1802.97 5197.72,1790.53 5172.83,1802.97 5185.27,1778.08 5172.83,1753.2 ; 5172.83,1952.29 5222.6,1952.29 5197.72,1902.52 5172.83,1952.29 ; 5172.83,2201.16 5222.6,2201.16 5222.6,2250.93 5172.83,2250.93 5172.83,2201.16 ; 5182.78,1165.87 5212.65,1165.87 5212.65,1195.73 5182.78,1195.73 5182.78,1165.87
  lines w12: 5105,1111.12 7223.02,1111.12 ; 5105,2305.68 7223.02,2305.68 ; 5475.36,961.8 5475.36,2455 ; 5832.36,961.8 5832.36,2455 ; 6493.93,961.8 6493.93,2455 ; 6778.07,961.8 6778.07,2455 ; 5105,961.8 7223.02,961.8 7223.02,2455 5105,2455 5105,961.8
  text "Symbol" at 5194.59,2350.48 h72
  text "Quantity" at 5520.16,2350.48 h72
  text "Finished Hole Size" at 5877.16,2350.48 h72
  text "Plated" at 6538.72,2350.48 h72
  text "Hole Type" at 6822.86,2350.48 h72
  text "141" at 5520.16,2201.16 h60
  text "12.00mil (0.305mm)" at 5877.16,2201.16 h60
  text "PTH" at 6538.72,2201.16 h60
  text "Round" at 6822.86,2201.16 h60
  text "5" at 5520.16,2051.84 h60
  text "26.00mil (0.660mm)" at 5877.16,2051.84 h60
  text "PTH" at 6538.72,2051.84 h60
  text "Round" at 6822.86,2051.84 h60
  text "5" at 5520.16,1902.52 h60
  text "28.00mil (0.711mm)" at 5877.16,1902.52 h60
  text "PTH" at 6538.72,1902.52 h60
  text "Round" at 6822.86,1902.52 h60
  text "12" at 5520.16,1753.2 h60
  text "39.37mil (1.000mm)" at 5877.16,1753.2 h60
  text "PTH" at 6538.72,1753.2 h60
  text "Round" at 6822.86,1753.2 h60
  text "9" at 5520.16,1603.88 h60
  text "40.00mil (1.016mm)" at 5877.16,1603.88 h60
  text "PTH" at 6538.72,1603.88 h60
  text "Round" at 6822.86,1603.88 h60
  text "42" at 5520.16,1454.56 h60
  text "45.28mil (1.150mm)" at 5877.16,1454.56 h60
  text "PTH" at 6538.72,1454.56 h60
  text "Round" at 6822.86,1454.56 h60
  text "3" at 5520.16,1305.24 h60
  text "55.12mil (1.400mm)" at 5877.16,1305.24 h60
  text "PTH" at 6538.72,1305.24 h60
  text "Round" at 6822.86,1305.24 h60
  text "3" at 5520.16,1155.92 h60
  text "39.37mil (1.000mm)" at 5877.16,1155.92 h60
  text "PTH" at 6538.72,1155.92 h60
  text "Slot" at 6822.86,1155.92 h60
  text "220 Total" at 5520.16,1006.6 h60
  text ".legend" at 5122.5,725.5 h60
  text "Drill Table" at 5147.5,540.5 h60
  text ".Layer_Name" at 577,-858.49 h60

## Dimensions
1350,1320 to 3150,1320 on M2 Board Dimensions
3047,1305 to 4500,1700 on M2 Board Dimensions
0,0 to -5,1690 on M2 Board Dimensions
4500,0 to 0,0 on M2 Board Dimensions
